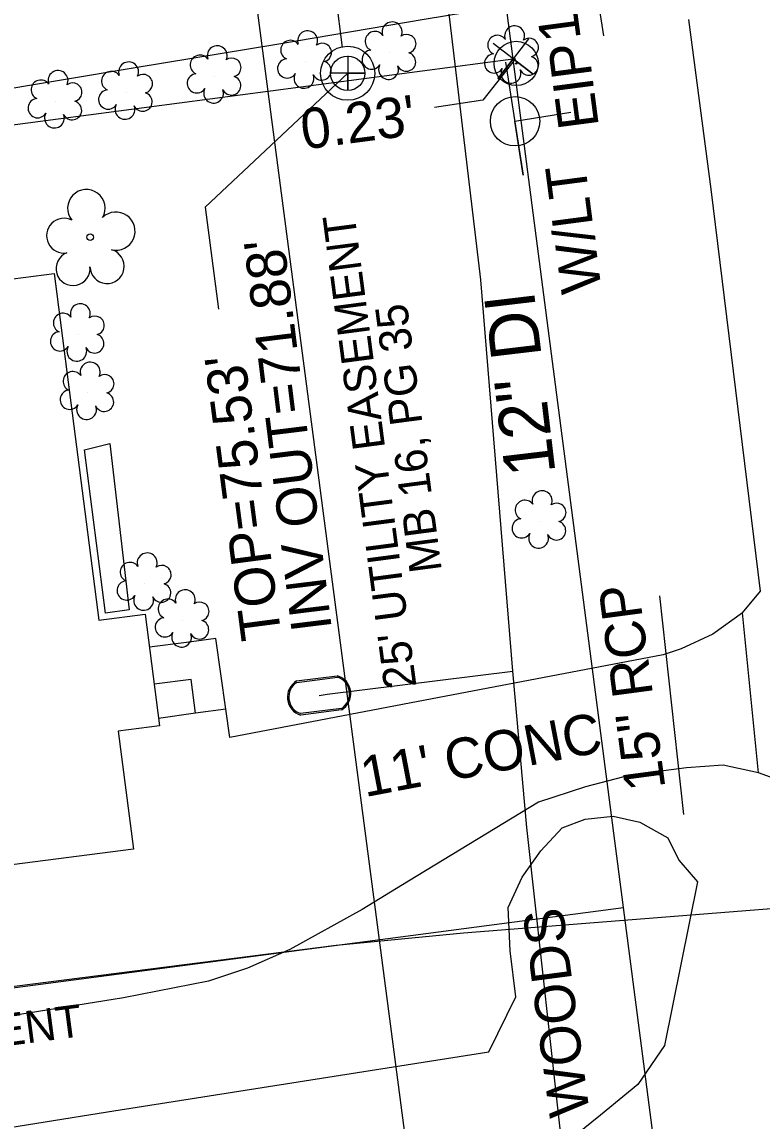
# Model space of a CAD drawing. Extents: x 2364404 to 2371833, y 798876 to 809754.
# Drawn here: x 2368422.3 to 2368495.8, y 806930.7 to 807039.8 of the extents above; entities that cross this region are included whole.
import ezdxf

# ---------------------------------------------------------------- set-up
doc = ezdxf.new("R2010")
doc.units = 0
for name, color, linetype in [('Exist Building', 7, 'Continuous'), ('Exist Other Culture Area Outline', 7, 'Continuous'), ('Exist Property Corner CELL', 7, 'Continuous'), ('Exist Property Iron Pin CELL', 7, 'Continuous'), ('Exist Property Iron Pin Text', 7, 'Continuous'), ('Exist Property Line', 7, 'Continuous'), ('Exist Property Line Leader', 7, 'Continuous'), ('Exist Property Line Text', 7, 'Continuous'), ('Exist Right of Way Easement Line', 7, 'Continuous'), ('Exist Right of Way Easement Line Text', 7, 'Continuous'), ('Exist Right of Way Line', 7, 'Continuous'), ('Exist Roads EOP', 7, 'Continuous'), ('Exist Roads EOP Other', 7, 'Continuous'), ('Exist Roads EOP Other Text', 7, 'Continuous'), ('Exist Structure Minor Pipes RCP 15 Inch', 7, 'Continuous'), ('Exist Structure Minor Pipes RCP 15 Inch Text', 7, 'Continuous'), ('Exist Utilities Gas UG Line SUE LOS B', 7, 'Continuous'), ('Exist Utilities Power Joint Use Telephone CELL', 7, 'Continuous'), ('Exist Utilities Power Joint Use Telephone Text', 7, 'Continuous'), ('Exist Utilities Sanitary Sewer Manhole CELL', 7, 'Continuous'), ('Exist Utilities Sanitary Sewer Manhole Leader', 7, 'Continuous'), ('Exist Utilities Sanitary Sewer Manhole Top Elevation', 7, 'Continuous'), ('Exist Utilities Sanitary Sewer UG Line', 7, 'Continuous'), ('Exist Utilities Sanitary Sewer UG Line Invert Elevation', 7, 'Continuous'), ('Exist Utilities Water Meter CELL', 7, 'Continuous'), ('Exist Utilities Water UG Line SUE LOS B', 7, 'Continuous'), ('Exist Utilities Water UG Line SUE LOS B Text', 7, 'Continuous'), ('Exist Vegetation Hedge Row', 7, 'Continuous'), ('Exist Vegetation Shrub CELL', 7, 'Continuous'), ('Exist Vegetation Tree CELL', 7, 'Continuous'), ('Exist Vegetation Woods Line', 7, 'Continuous'), ('Exist Vegetation Woods Line Text', 7, 'Continuous')]:
    doc.layers.add(name, color=color, linetype=linetype)

msp = doc.modelspace()

# ---------------------------------------------------------------- linework, layer by layer
at = {"layer": 'Exist Building'}
msp.add_lwpolyline([(2368425.53, 807014.81), (2368429.96, 806980.41), (2368434.57, 806981), (2368436, 806969.91), (2368431.89, 806969.38), (2368433.4, 806957.68), (2368415.91, 806955.42), (2368417.21, 806945.33), (2368403.91, 806943.61), (2368403.39, 806943.54), (2368394.71, 807010.84)], close=True, dxfattribs=at)
at = {"layer": 'Exist Other Culture Area Outline'}
for points in [[(2368442.6, 806971.57), (2368441.59, 806978.59), (2368438.67, 806978.17), (2368435, 806977.72)], [(2368439.56, 806971.16), (2368439.13, 806974.5), (2368435.47, 806974.04)]]:
    msp.add_lwpolyline(points, dxfattribs=at)
at = {"layer": 'Exist Property Corner CELL'}
msp.add_line((2368471.14, 807036.11), (2368471.14, 807036.11), dxfattribs=at)
msp.add_lwpolyline([(2368472.66, 807038.09), (2368469.61, 807034.12), (2368471.14, 807036.11), (2368473.12, 807034.59), (2368469.15, 807037.63)], dxfattribs=at)
at = {"layer": 'Exist Property Iron Pin CELL'}
for radius in [2.2, 0.0707]:
    msp.add_circle((2368471.43, 807035.66), radius, dxfattribs=at)
at = {"layer": 'Exist Property Line'}
for p, q in [((2368306.01, 807014.42), (2368471.14, 807036.11)), ((2368471.14, 807036.11), (2368471.37, 807036.14))]:
    msp.add_line(p, q, dxfattribs=at)
at = {"layer": 'Exist Property Line Leader'}
msp.add_lwpolyline([(2368471.31, 807036.1), (2368468.11, 807032.01), (2368463.3, 807031.29)], dxfattribs=at)
at = {"layer": 'Exist Right of Way Easement Line'}
for p, q in [((2368511.71, 806538.64), (2368344.2, 807814.14)), ((2368317.02, 806930.19), (2368482.09, 806951.87))]:
    msp.add_line(p, q, dxfattribs=at)
at = {"layer": 'Exist Right of Way Line'}
msp.add_line((2368533.02, 806560.45), (2368368.2, 807827.36), dxfattribs=at)
at = {"layer": 'Exist Roads EOP'}
msp.add_lwpolyline([(2368542.08, 806633.94), (2368537.65, 806665.16), (2368536.24, 806665.79), (2368533.02, 806685.33), (2368534.76, 806687.62), (2368527.71, 806739.03), (2368521.09, 806788.9), (2368519.37, 806799.41), (2368518.6, 806801.72), (2368517.16, 806802.97), (2368515.73, 806814.41), (2368516.71, 806816.13), (2368517.13, 806818.19), (2368509.17, 806879.16), (2368497.78, 806964.4), (2368495.51, 806965.25), (2368493.89, 806981.12), (2368495.71, 806983.28), (2368490.79, 807023.19), (2368488.57, 807040.03)], dxfattribs=at)
at = {"layer": 'Exist Roads EOP Other'}
for points in [[(2368484.84, 807042.27), (2368478.86, 807041.92), (2368472.79, 807041.75), (2368462.27, 807040.03), (2368447.66, 807037.55), (2368433.79, 807035.27), (2368394.96, 807028.78), (2368393.77, 807038.77)], [(2368493.89, 806981.12), (2368490.97, 806979), (2368487.8, 806977.55), (2368486.01, 806976.96), (2368460.13, 806972.02), (2368442.99, 806968.76), (2368442.6, 806971.57), (2368439.56, 806971.16), (2368435.91, 806970.62)], [(2368495.51, 806965.25), (2368491.99, 806966.01), (2368488.36, 806965.74), (2368482.76, 806965.01), (2368478.3, 806963.84), (2368473.64, 806962.32), (2368460.73, 806954.49), (2368456.12, 806951.69), (2368448.94, 806947.72), (2368444.73, 806945.84), (2368440.85, 806944.57), (2368432.43, 806942.91), (2368415.49, 806940.2), (2368414.86, 806945.02)]]:
    msp.add_lwpolyline(points, dxfattribs=at)
at = {"layer": 'Exist Structure Minor Pipes RCP 15 Inch'}
for p, q in [((2368477.01, 807058.64), (2368480.1, 807038.41)), ((2368485.67, 806982.8), (2368488.03, 806961.1))]:
    msp.add_line(p, q, dxfattribs=at)
at = {"layer": 'Exist Utilities Gas UG Line SUE LOS B'}
msp.add_lwpolyline([(2368401.85, 806959.7), (2368401.46, 806948.68), (2368403.53, 806945.42), (2368418.17, 806943.63), (2368453.54, 806948.15), (2368466.19, 806949.36), (2368497.18, 806951.81), (2368498, 806951.99), (2368522.59, 806953.22), (2368522.83, 806953.25)], dxfattribs=at)
at = {"layer": 'Exist Utilities Power Joint Use Telephone CELL'}
msp.add_line((2368471.3, 807029.92), (2368471.3, 807029.92), dxfattribs=at)
msp.add_lwpolyline([(2368470.37, 807035.79), (2368472.12, 807024.58), (2368471.29, 807029.92), (2368476.86, 807030.81)], dxfattribs=at)
msp.add_circle((2368471.31, 807029.92), 2.45, dxfattribs=at)
at = {"layer": 'Exist Utilities Sanitary Sewer Manhole CELL'}
msp.add_lwpolyline([(2368454.69, 807036.41), (2368454.69, 807032.98), (2368454.69, 807034.69), (2368456.41, 807034.69), (2368452.98, 807034.69)], dxfattribs=at)
for radius in [2.69, 1.71]:
    msp.add_circle((2368454.69, 807034.69), radius, dxfattribs=at)
at = {"layer": 'Exist Utilities Sanitary Sewer Manhole Leader'}
msp.add_lwpolyline([(2368454.69, 807034.69), (2368440.54, 807021.39), (2368441.87, 807011.26)], dxfattribs=at)
at = {"layer": 'Exist Utilities Sanitary Sewer UG Line'}
msp.add_line((2368454.19, 807037.23), (2368403.54, 807422.66), dxfattribs=at)
at = {"layer": 'Exist Utilities Water Meter CELL'}
msp.add_line((2368451.85, 806972.93), (2368451.85, 806972.93), dxfattribs=at)
for points in [[(2368449.62, 806974.36), (2368453.66, 806974.87)], [(2368449.64, 806974.22), (2368453.68, 806974.73)], [(2368454.07, 806971.63), (2368450, 806971.12)], [(2368454.09, 806971.5), (2368450.02, 806970.98)]]:
    msp.add_lwpolyline(points, dxfattribs=at)
for centre, radius, start, end in [((2368450.56, 806972.76), 1.86, 120.3975, 253.1988), ((2368450.57, 806972.76), 1.73, 122.5204, 251.0018), ((2368453.14, 806973.09), 1.86, 300.8678, 73.5278), ((2368453.15, 806973.09), 1.73, 302.3466, 72.0923)]:
    msp.add_arc(centre, radius, start, end, dxfattribs=at)
at = {"layer": 'Exist Utilities Water UG Line SUE LOS B'}
for points in [[(2368519.2, 806620.08), (2368510.97, 806683.25), (2368505.65, 806723.63), (2368499.9, 806767.95), (2368493.34, 806816.93), (2368491.14, 806831.44), (2368484.04, 806869.78), (2368477.82, 806911.63), (2368472.48, 806959.83), (2368471.08, 806975.35), (2368467.91, 807014.19), (2368461.16, 807070.94), (2368455.32, 807116.26), (2368449.6, 807161.65), (2368446.12, 807187.28), (2368441.35, 807211.9), (2368441.09, 807221.64), (2368437.56, 807243.96), (2368435.61, 807263.12), (2368428.93, 807315.03)], [(2368451.85, 806972.93), (2368452.65, 806973.04), (2368471.08, 806975.35)]]:
    msp.add_lwpolyline(points, dxfattribs=at)
at = {"layer": 'Exist Vegetation Hedge Row'}
msp.add_line((2368431.06, 806997.93), (2368432.99, 806981.43), dxfattribs=at)
msp.add_lwpolyline([(2368432.99, 806981.43), (2368430.64, 806981.09), (2368428.55, 806997.3), (2368431.06, 806997.93)], dxfattribs=at)
at = {"layer": 'Exist Vegetation Shrub CELL'}
for p, q in [((2368458.88, 807036.74), (2368458.88, 807036.74)), ((2368471.04, 807036.36), (2368471.04, 807036.36)), ((2368450.48, 807035.87), (2368450.48, 807035.87)), ((2368441.5, 807034.39), (2368441.5, 807034.39)), ((2368425.69, 807031.93), (2368425.69, 807031.93)), ((2368432.7, 807032.78), (2368432.7, 807032.78)), ((2368427.91, 807008.78), (2368427.91, 807008.78)), ((2368428.88, 807002.98), (2368428.88, 807002.98)), ((2368473.77, 806990.22), (2368473.77, 806990.22)), ((2368434.54, 806984.04), (2368434.54, 806984.04)), ((2368438.32, 806980.39), (2368438.32, 806980.39))]:
    msp.add_line(p, q, dxfattribs=at)
for centre, radius, start, end in [((2368459.1, 807038.79), 0.99, 334.8391, 200.4717), ((2368450.71, 807037.91), 0.99, 334.8391, 200.4717), ((2368457.39, 807037.87), 0.968, 35.8908, 245.4216), ((2368460.55, 807037.61), 0.929, 284.4567, 126.0861), ((2368469.56, 807037.49), 0.968, 35.8908, 245.4216), ((2368471.27, 807038.4), 0.99, 334.8391, 200.4717), ((2368441.73, 807036.43), 0.99, 334.8391, 200.4717), ((2368449, 807036.99), 0.968, 35.8908, 245.4216), ((2368452.15, 807036.74), 0.929, 284.4567, 126.0861), ((2368472.71, 807037.23), 0.929, 284.4567, 126.0861), ((2368440.02, 807035.52), 0.968, 35.8908, 245.4216), ((2368443.17, 807035.26), 0.929, 284.4567, 126.0861), ((2368457.07, 807036.04), 0.955, 95.1099, 327.9534), ((2368460.51, 807035.82), 0.937, 204.9913, 73.4601), ((2368469.24, 807035.66), 0.955, 95.1099, 327.9534), ((2368472.68, 807035.43), 0.937, 204.9913, 73.4601), ((2368432.93, 807034.82), 0.99, 334.8391, 200.4717), ((2368448.68, 807035.16), 0.955, 95.1099, 327.9534), ((2368452.12, 807034.94), 0.937, 204.9913, 73.4601), ((2368458.75, 807035.06), 0.984, 151.2797, 21.387), ((2368470.91, 807034.68), 0.984, 151.2797, 21.387), ((2368424.21, 807033.05), 0.968, 35.8908, 245.4216), ((2368425.92, 807033.97), 0.99, 334.8391, 200.4717), ((2368431.21, 807033.91), 0.968, 35.8908, 245.4216), ((2368434.37, 807033.65), 0.929, 284.4567, 126.0861), ((2368439.7, 807033.69), 0.955, 95.1099, 327.9534), ((2368443.14, 807033.46), 0.937, 204.9913, 73.4601), ((2368450.35, 807034.18), 0.984, 151.2797, 21.387), ((2368427.36, 807032.8), 0.929, 284.4567, 126.0861), ((2368430.9, 807032.08), 0.955, 95.1099, 327.9534), ((2368441.37, 807032.71), 0.984, 151.2797, 21.387), ((2368423.89, 807031.22), 0.955, 95.1099, 327.9534), ((2368427.33, 807031), 0.937, 204.9913, 73.4601), ((2368434.33, 807031.85), 0.937, 204.9913, 73.4601), ((2368425.56, 807030.24), 0.984, 151.2797, 21.387), ((2368432.57, 807031.1), 0.984, 151.2797, 21.387), ((2368428.13, 807010.82), 0.99, 334.8391, 200.4717), ((2368426.42, 807009.9), 0.968, 35.8908, 245.4216), ((2368429.58, 807009.65), 0.929, 284.4567, 126.0861), ((2368426.11, 807008.07), 0.955, 95.1099, 327.9534), ((2368429.54, 807007.85), 0.937, 204.9913, 73.4601), ((2368427.78, 807007.09), 0.984, 151.2797, 21.387), ((2368429.11, 807005.02), 0.99, 334.8391, 200.4717), ((2368427.39, 807004.11), 0.968, 35.8908, 245.4216), ((2368430.55, 807003.85), 0.929, 284.4567, 126.0861), ((2368427.08, 807002.28), 0.955, 95.1099, 327.9534), ((2368430.51, 807002.05), 0.937, 204.9913, 73.4601), ((2368428.75, 807001.3), 0.984, 151.2797, 21.387), ((2368474, 806992.26), 0.99, 334.8391, 200.4717), ((2368472.29, 806991.34), 0.968, 35.8908, 245.4216), ((2368475.45, 806991.08), 0.929, 284.4567, 126.0861), ((2368471.97, 806989.51), 0.955, 95.1099, 327.9534), ((2368475.41, 806989.29), 0.937, 204.9913, 73.4601), ((2368473.65, 806988.53), 0.984, 151.2797, 21.387), ((2368434.77, 806986.08), 0.99, 334.8391, 200.4717), ((2368433.06, 806985.17), 0.968, 35.8908, 245.4216), ((2368436.22, 806984.91), 0.929, 284.4567, 126.0861), ((2368432.74, 806983.34), 0.955, 95.1099, 327.9534), ((2368436.18, 806983.11), 0.937, 204.9913, 73.4601), ((2368434.42, 806982.36), 0.984, 151.2797, 21.387), ((2368438.55, 806982.43), 0.99, 334.8391, 200.4717), ((2368436.83, 806981.52), 0.968, 35.8908, 245.4216), ((2368439.99, 806981.26), 0.929, 284.4567, 126.0861), ((2368436.52, 806979.69), 0.955, 95.1099, 327.9534), ((2368439.95, 806979.46), 0.937, 204.9913, 73.4601), ((2368438.19, 806978.71), 0.984, 151.2797, 21.387)]:
    msp.add_arc(centre, radius, start, end, dxfattribs=at)
at = {"layer": 'Exist Vegetation Tree CELL'}
msp.add_line((2368429.12, 807018.42), (2368429.12, 807018.42), dxfattribs=at)
msp.add_circle((2368429.12, 807018.42), 0.326, dxfattribs=at)
for centre, radius, start, end in [((2368428.73, 807021.29), 1.86, 330.1651, 219.7134), ((2368431.67, 807019.01), 1.9, 257.1011, 134.1999), ((2368426.51, 807018.57), 1.73, 62.6636, 279.3457), ((2368427.41, 807015.3), 1.69, 111.5671, 6.231), ((2368430.79, 807015.52), 1.7, 181.2822, 74.56)]:
    msp.add_arc(centre, radius, start, end, dxfattribs=at)
at = {"layer": 'Exist Vegetation Woods Line'}
for points in [[(2368359.15, 806964.43), (2368364.89, 806966.3), (2368371.14, 806963.81), (2368392.64, 806946.04), (2368403.49, 806936.32), (2368410.84, 806932.13), (2368418.4, 806929.6), (2368430.84, 806931.58), (2368468.71, 806937.54), (2368471.4, 806943.01), (2368470.84, 806947.58), (2368470.63, 806951.87), (2368472.01, 806954.87), (2368473.86, 806957.5), (2368476, 806959.79), (2368478.29, 806960.63), (2368481.05, 806960.93), (2368483.7, 806960.35), (2368486.49, 806958.78), (2368487.57, 806956.58), (2368489.43, 806954.43)], [(2368489.43, 806954.43), (2368486.17, 806938.17), (2368483.5, 806934.29), (2368479.81, 806931.25), (2368475.84, 806928.06), (2368471.81, 806924.28), (2368467.72, 806920.12), (2368466.26, 806916.29), (2368467.94, 806914.27), (2368472.65, 806912.77), (2368481.91, 806911.84), (2368484.23, 806910.16), (2368484.86, 806907), (2368484.12, 806903.86), (2368472.79, 806890.72), (2368467.97, 806886.47), (2368463.28, 806886.59), (2368458.36, 806890.56), (2368446.61, 806906.29), (2368443.97, 806909.93), (2368439.5, 806916.07), (2368431.1, 806924.19), (2368402.11, 806919.31), (2368365.97, 806914.05)]]:
    msp.add_lwpolyline(points, dxfattribs=at)

# ---------------------------------------------------------------- texts
at = {"layer": 'Exist Property Iron Pin Text'}
msp.add_text('EIP', height=4, rotation=97.4798, dxfattribs=at).set_placement((2368479.65, 807029.42))
at = {"layer": 'Exist Property Line Text'}
msp.add_text("0.23'", height=4, rotation=7.4817, dxfattribs=at).set_placement((2368450.3, 807027.11))
at = {"layer": 'Exist Right of Way Easement Line Text'}
for s, rotation, p in [("25' UTILITY EASEMENT", 97.4798, (2368461.53, 806973.81)), ('MB 16, PG 35', 97.4798, (2368464.05, 806985.32)), ("40' DRAINAGE EASEMENT", 7.4817, (2368375.09, 806932.11))]:
    msp.add_text(s, height=3.2, rotation=rotation, dxfattribs=at).set_placement(p)
at = {"layer": 'Exist Roads EOP Other Text'}
msp.add_text("11' CONC", height=4, rotation=10.8068, dxfattribs=at).set_placement((2368456.4, 806962.82))
at = {"layer": 'Exist Structure Minor Pipes RCP 15 Inch Text'}
for p in [(2368477.86, 807038.1), (2368486.26, 806963.74)]:
    msp.add_text('15" RCP', height=4, rotation=97.5936, dxfattribs=at).set_placement(p)
at = {"layer": 'Exist Utilities Power Joint Use Telephone Text'}
msp.add_text('W/LT', height=4, rotation=97.4798, dxfattribs=at).set_placement((2368479.92, 807013.14))
at = {"layer": 'Exist Utilities Sanitary Sewer Manhole Top Elevation'}
msp.add_text("TOP=75.53'", height=4, rotation=97.4798, dxfattribs=at).set_placement((2368448.13, 806978.69))
at = {"layer": 'Exist Utilities Sanitary Sewer UG Line Invert Elevation'}
msp.add_text("INV OUT=71.88'", height=4, rotation=97.0223, dxfattribs=at).set_placement((2368453.12, 806979.53))
at = {"layer": 'Exist Utilities Water UG Line SUE LOS B Text'}
msp.add_text('12" DI', height=5, rotation=96.7799, dxfattribs=at).set_placement((2368475.34, 806995.01))
at = {"layer": 'Exist Vegetation Woods Line Text'}
msp.add_text('WOODS', height=4, rotation=97.4798, dxfattribs=at).set_placement((2368478.74, 806931.39))

doc.saveas('drawing.dxf')
